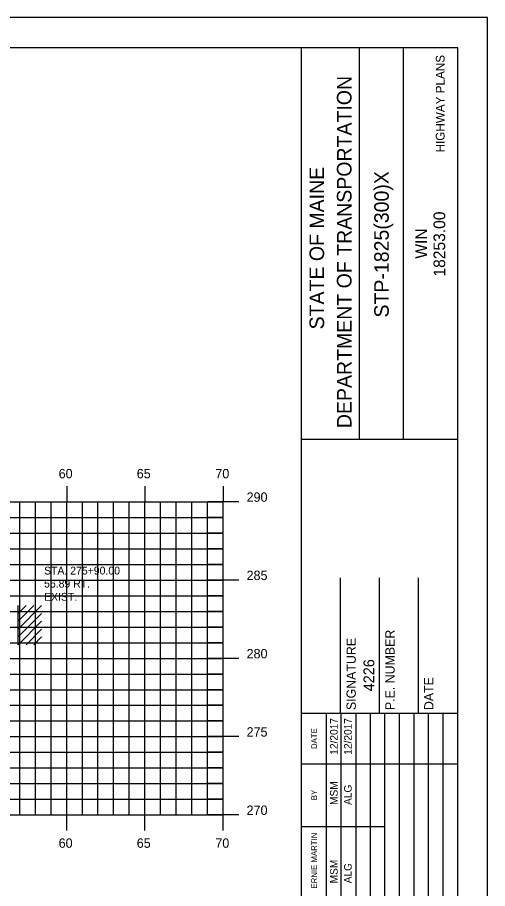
# Model space of a CAD drawing. Extents: x 853563 to 853733, y 366268 to 366378.
# Drawn here: x 853702.6 to 853732.7, y 366322.5 to 366378.2 of the extents above; entities that cross this region are included whole.
import ezdxf

# ---------------------------------------------------------------- set-up
doc = ezdxf.new("R2010")
doc.units = 0
for name, color, linetype in [('ANNOTATION', 7, 'Continuous'), ('BORDER', 7, 'Continuous'), ('D_Text_Monospaced', 7, 'Continuous'), ('H_V ANNOTATION', 7, 'Continuous'), ('HIGHWAY_TITLE', 7, 'Continuous'), ('MAJOR', 7, 'Continuous'), ('MINOR', 7, 'Continuous'), ('PLOT BOUNDARY', 7, 'Continuous'), ('S_Buildings', 7, 'Continuous')]:
    doc.layers.add(name, color=color, linetype=linetype)

msp = doc.modelspace()

# ---------------------------------------------------------------- linework, layer by layer
at = {"layer": 'BORDER'}
for p, q in [((853730.768, 366376.236), (853570.768, 366376.236)), ((853720.768, 366271.236), (853720.768, 366376.239)), ((853724.496, 366351.234), (853724.496, 366376.234)), ((853727.291, 366351.234), (853727.291, 366376.234)), ((853730.768, 366271.236), (853730.768, 366376.236)), ((853720.769, 366351.231), (853730.768, 366351.231)), ((853723.268, 366333.739), (853723.268, 366342.387)), ((853725.768, 366333.739), (853725.768, 366342.387)), ((853728.268, 366333.739), (853728.268, 366342.387)), ((853720.768, 366333.739), (853730.768, 366333.739))]:
    msp.add_line(p, q, dxfattribs=at)
for points in [[(853722.383, 366330.489), (853722.383, 366333.739)], [(853723.315, 366316.242), (853723.315, 366333.739)], [(853724.247, 366333.739), (853724.247, 366316.242)], [(853725.179, 366316.242), (853725.179, 366333.739)], [(853726.11, 366316.242), (853726.11, 366333.739)], [(853727.042, 366316.242), (853727.042, 366333.739)], [(853727.974, 366316.242), (853727.974, 366333.739)], [(853728.905, 366316.242), (853728.905, 366333.739)], [(853729.837, 366316.242), (853729.837, 366333.739)], [(853722.383, 366316.242), (853722.383, 366333.033)], [(853720.768, 366330.489), (853730.768, 366330.489)], [(853720.768, 366326.489), (853722.383, 366326.489)], [(853722.383, 366326.489), (853726.109, 366326.489)]]:
    msp.add_lwpolyline(points, dxfattribs=at)
at = {"layer": 'MAJOR'}
for p, q in [((853705.768, 366348.238), (853705.768, 366347.236)), ((853710.768, 366348.238), (853710.768, 366347.236)), ((853715.768, 366348.238), (853715.768, 366347.236)), ((853575.768, 366347.236), (853715.768, 366347.236)), ((853575.768, 366347.236), (853715.768, 366347.236)), ((853705.768, 366327.236), (853705.768, 366347.236)), ((853710.768, 366327.236), (853710.768, 366347.236)), ((853716.77, 366347.236), (853714.766, 366347.236)), ((853715.768, 366327.236), (853715.768, 366347.236)), ((853715.768, 366327.236), (853715.768, 366347.236)), ((853575.768, 366342.236), (853715.768, 366342.236)), ((853716.77, 366342.236), (853714.766, 366342.236)), ((853575.768, 366337.236), (853715.768, 366337.236)), ((853716.77, 366337.236), (853714.766, 366337.236)), ((853575.768, 366332.236), (853715.768, 366332.236)), ((853716.77, 366332.236), (853714.766, 366332.236)), ((853575.768, 366327.236), (853715.768, 366327.236)), ((853575.768, 366327.236), (853715.768, 366327.236)), ((853705.768, 366326.234), (853705.768, 366327.236)), ((853710.768, 366326.234), (853710.768, 366327.236)), ((853716.77, 366327.236), (853714.766, 366327.236)), ((853715.768, 366326.234), (853715.768, 366327.236))]:
    msp.add_line(p, q, dxfattribs=at)
at = {"layer": 'MINOR'}
for p, q in [((853702.768, 366327.236), (853702.768, 366347.236)), ((853703.768, 366327.236), (853703.768, 366347.236)), ((853704.768, 366327.236), (853704.768, 366347.236)), ((853706.768, 366327.236), (853706.768, 366347.236)), ((853707.768, 366327.236), (853707.768, 366347.236)), ((853708.768, 366327.236), (853708.768, 366347.236)), ((853709.768, 366327.236), (853709.768, 366347.236)), ((853711.768, 366327.236), (853711.768, 366347.236)), ((853712.768, 366327.236), (853712.768, 366347.236)), ((853713.768, 366327.236), (853713.768, 366347.236)), ((853714.768, 366327.236), (853714.768, 366347.236)), ((853575.768, 366346.236), (853715.768, 366346.236)), ((853715.768, 366346.236), (853714.766, 366346.236)), ((853575.768, 366345.236), (853715.768, 366345.236)), ((853715.768, 366345.236), (853714.766, 366345.236)), ((853575.768, 366344.236), (853715.768, 366344.236)), ((853715.768, 366344.236), (853714.766, 366344.236)), ((853575.768, 366343.236), (853715.768, 366343.236)), ((853715.768, 366343.236), (853714.766, 366343.236)), ((853575.768, 366341.236), (853715.768, 366341.236)), ((853715.768, 366341.236), (853714.766, 366341.236)), ((853575.768, 366340.236), (853715.768, 366340.236)), ((853715.768, 366340.236), (853714.766, 366340.236)), ((853575.768, 366339.236), (853715.768, 366339.236)), ((853715.768, 366339.236), (853714.766, 366339.236)), ((853575.768, 366338.236), (853715.768, 366338.236)), ((853715.768, 366338.236), (853714.766, 366338.236)), ((853575.768, 366336.236), (853715.768, 366336.236)), ((853715.768, 366336.236), (853714.766, 366336.236)), ((853575.768, 366335.236), (853715.768, 366335.236)), ((853715.768, 366335.236), (853714.766, 366335.236)), ((853575.768, 366334.236), (853715.768, 366334.236)), ((853715.768, 366334.236), (853714.766, 366334.236)), ((853575.768, 366333.236), (853715.768, 366333.236)), ((853715.768, 366333.236), (853714.766, 366333.236)), ((853575.768, 366331.236), (853715.768, 366331.236)), ((853715.768, 366331.236), (853714.766, 366331.236)), ((853575.768, 366330.236), (853715.768, 366330.236)), ((853715.768, 366330.236), (853714.766, 366330.236)), ((853575.768, 366329.236), (853715.768, 366329.236)), ((853715.768, 366329.236), (853714.766, 366329.236)), ((853575.768, 366328.236), (853715.768, 366328.236)), ((853715.768, 366328.236), (853714.766, 366328.236))]:
    msp.add_line(p, q, dxfattribs=at)
at = {"layer": 'PLOT BOUNDARY'}
msp.add_lwpolyline([(853562.674, 366268.177), (853732.674, 366268.177), (853732.674, 366378.177), (853562.674, 366378.177)], close=True, dxfattribs=at)
at = {"layer": 'S_Buildings'}
for p, q in [((853702.657, 366338.093), (853702.657, 366340.62)), ((853702.657, 366339.11), (853704.166, 366340.62)), ((853702.657, 366339.602), (853703.674, 366340.62)), ((853702.657, 366340.095), (853703.181, 366340.62)), ((853702.657, 366338.618), (853704.166, 366340.095)), ((853702.657, 366338.093), (853704.166, 366339.602)), ((853703.181, 366338.093), (853704.166, 366339.11)), ((853703.674, 366338.093), (853704.166, 366338.618))]:
    msp.add_line(p, q, dxfattribs=at)

# ---------------------------------------------------------------- texts
at = {"layer": 'ANNOTATION'}
msp.add_text('4226', height=0.69, rotation=90, dxfattribs=at).set_placement((853725.432, 366335.13))
at = {"layer": 'BORDER'}
for s, height, p in [('DEPARTMENT OF TRANSPORTATION', 0.93176, (853723.975, 366351.942)), ('STATE OF MAINE', 0.93176, (853722.223, 366358.248)), ('STP-1825(300)X', 0.93176, (853726.36, 366359.008)), ('18253.00', 0.7453, (853729.963, 366361.623)), ('WIN', 0.7453, (853728.804, 366362.766)), ('P.E. NUMBER', 0.59055, (853726.728, 366333.932)), ('SIGNATURE', 0.5906, (853724.248, 366333.932)), ('DATE', 0.5906, (853729.209, 366333.932)), ('12/2017', 0.4845, (853723.091, 366331.081)), ('12/2017', 0.4845, (853723.985, 366331.081)), ('DATE', 0.3714, (853721.772, 366331.445)), ('MSM', 0.4845, (853723.091, 366327.872)), ('ALG', 0.4845, (853723.985, 366327.872)), ('BY', 0.3714, (853721.772, 366328.174)), ('ERNIE MARTIN', 0.37275, (853721.772, 366322.531)), ('MSM', 0.4845, (853723.091, 366322.863)), ('ALG', 0.4845, (853723.985, 366322.863))]:
    msp.add_text(s, height=height, rotation=90, dxfattribs=at).set_placement(p)
at = {"layer": 'D_Text_Monospaced'}
for s, height, p in [('STA. 275+90.00', 0.49998, (853704.323, 366342.592)), ('56.89 RT.', 0.5, (853704.323, 366341.758)), ('EXIST. ', 0.5, (853704.323, 366340.918))]:
    msp.add_text(s, height=height, dxfattribs=at).set_placement(p)
at = {"layer": 'H_V ANNOTATION'}
for s, p in [('60', (853705.254, 366348.736)), ('65', (853710.246, 366348.736)), ('70', (853715.27, 366348.736)), ('290', (853717.268, 366347.236)), ('285', (853717.268, 366342.236)), ('280', (853717.268, 366337.236)), ('275', (853717.268, 366332.236)), ('270', (853717.268, 366327.236)), ('60', (853705.254, 366325.136)), ('65', (853710.246, 366325.136)), ('70', (853715.27, 366325.136))]:
    msp.add_text(s, height=0.6, dxfattribs=at).set_placement(p)
at = {"layer": 'HIGHWAY_TITLE'}
msp.add_text('HIGHWAY PLANS', height=0.55901, rotation=90, dxfattribs=at).set_placement((853729.926, 366369.552))

doc.saveas('drawing.dxf')
